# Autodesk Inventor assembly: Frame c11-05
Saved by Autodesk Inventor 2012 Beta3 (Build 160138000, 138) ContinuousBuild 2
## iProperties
Created: 2011-01
Part Number: Frame c11-05
Document SubType Name: Assembly
Designer: Beta-8540w
_FrameDoc: Frame Assembly
_Version: 15.0.0
Author: Beta-8540w
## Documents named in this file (20)
- C:\Inventor 2012 Essentials\Assemblies\Chapter 11\Frame\Frame c11-05.iam
- C:\Inventor 2012 Essentials\Assemblies\Chapter 11\Frame\Skeleton-c11-05.ipt
- C:\Inventor 2012 Essentials\Assemblies\Chapter 11\Frame\ANSI 2 1_4x5_16 00000001.ipt
- ANSI 2 1_4x5_16 00000001.ipt
- C:\Inventor 2012 Essentials\Assemblies\Chapter 11\Frame\ANSI 3x3x3_16 00000019.ipt
- ANSI 3x3x3_16 00000019.ipt
- C:\Inventor 2012 Essentials\Assemblies\Chapter 11\Frame\ANSI 3x3x3_16 00000020.ipt
- ANSI 3x3x3_16 00000020.ipt
- C:\Inventor 2012 Essentials\Assemblies\Chapter 11\Frame\ANSI 3x3x3_16 00000021.ipt
- ANSI 3x3x3_16 00000021.ipt
- C:\Inventor 2012 Essentials\Assemblies\Chapter 11\Frame\ANSI 3x3x3_16 00000022.ipt
- ANSI 3x3x3_16 00000022.ipt
- C:\Inventor 2012 Essentials\Assemblies\Chapter 11\Frame\ANSI 3x3x3_16 00000023.ipt
- ANSI 3x3x3_16 00000023.ipt
- C:\Inventor 2012 Essentials\Assemblies\Chapter 11\Frame\ANSI 3x3x3_16 00000024.ipt
- ANSI 3x3x3_16 00000024.ipt
- C:\Inventor 2012 Essentials\Assemblies\Chapter 11\Frame\ANSI L 1.5 x 1.5 x 3_16 00000025.ipt
- ANSI L 1.5 x 1.5 x 3_16 00000025.ipt
- C:\Inventor 2012 Essentials\Assemblies\Chapter 11\Frame\ANSI L 1.5 x 1.5 x 3_16 00000026.ipt
- ANSI L 1.5 x 1.5 x 3_16 00000026.ipt
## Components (10 placed, 10 different names)
1. Frame Reference Model
2. ANSI 2 1_4x5_16 00000001:1
3. ANSI 3x3x3_16 00000019:1
4. ANSI 3x3x3_16 00000020:1
5. ANSI 3x3x3_16 00000021:1
6. ANSI 3x3x3_16 00000022:1
7. ANSI 3x3x3_16 00000023:1
8. ANSI 3x3x3_16 00000024:1
9. ANSI L 1.5 x 1.5 x 3_16 00000025:1
10. ANSI L 1.5 x 1.5 x 3_16 00000026:1
